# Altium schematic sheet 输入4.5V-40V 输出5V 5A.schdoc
size 384 x 220 mm; SheetNumber: 1; SheetTotal: 1
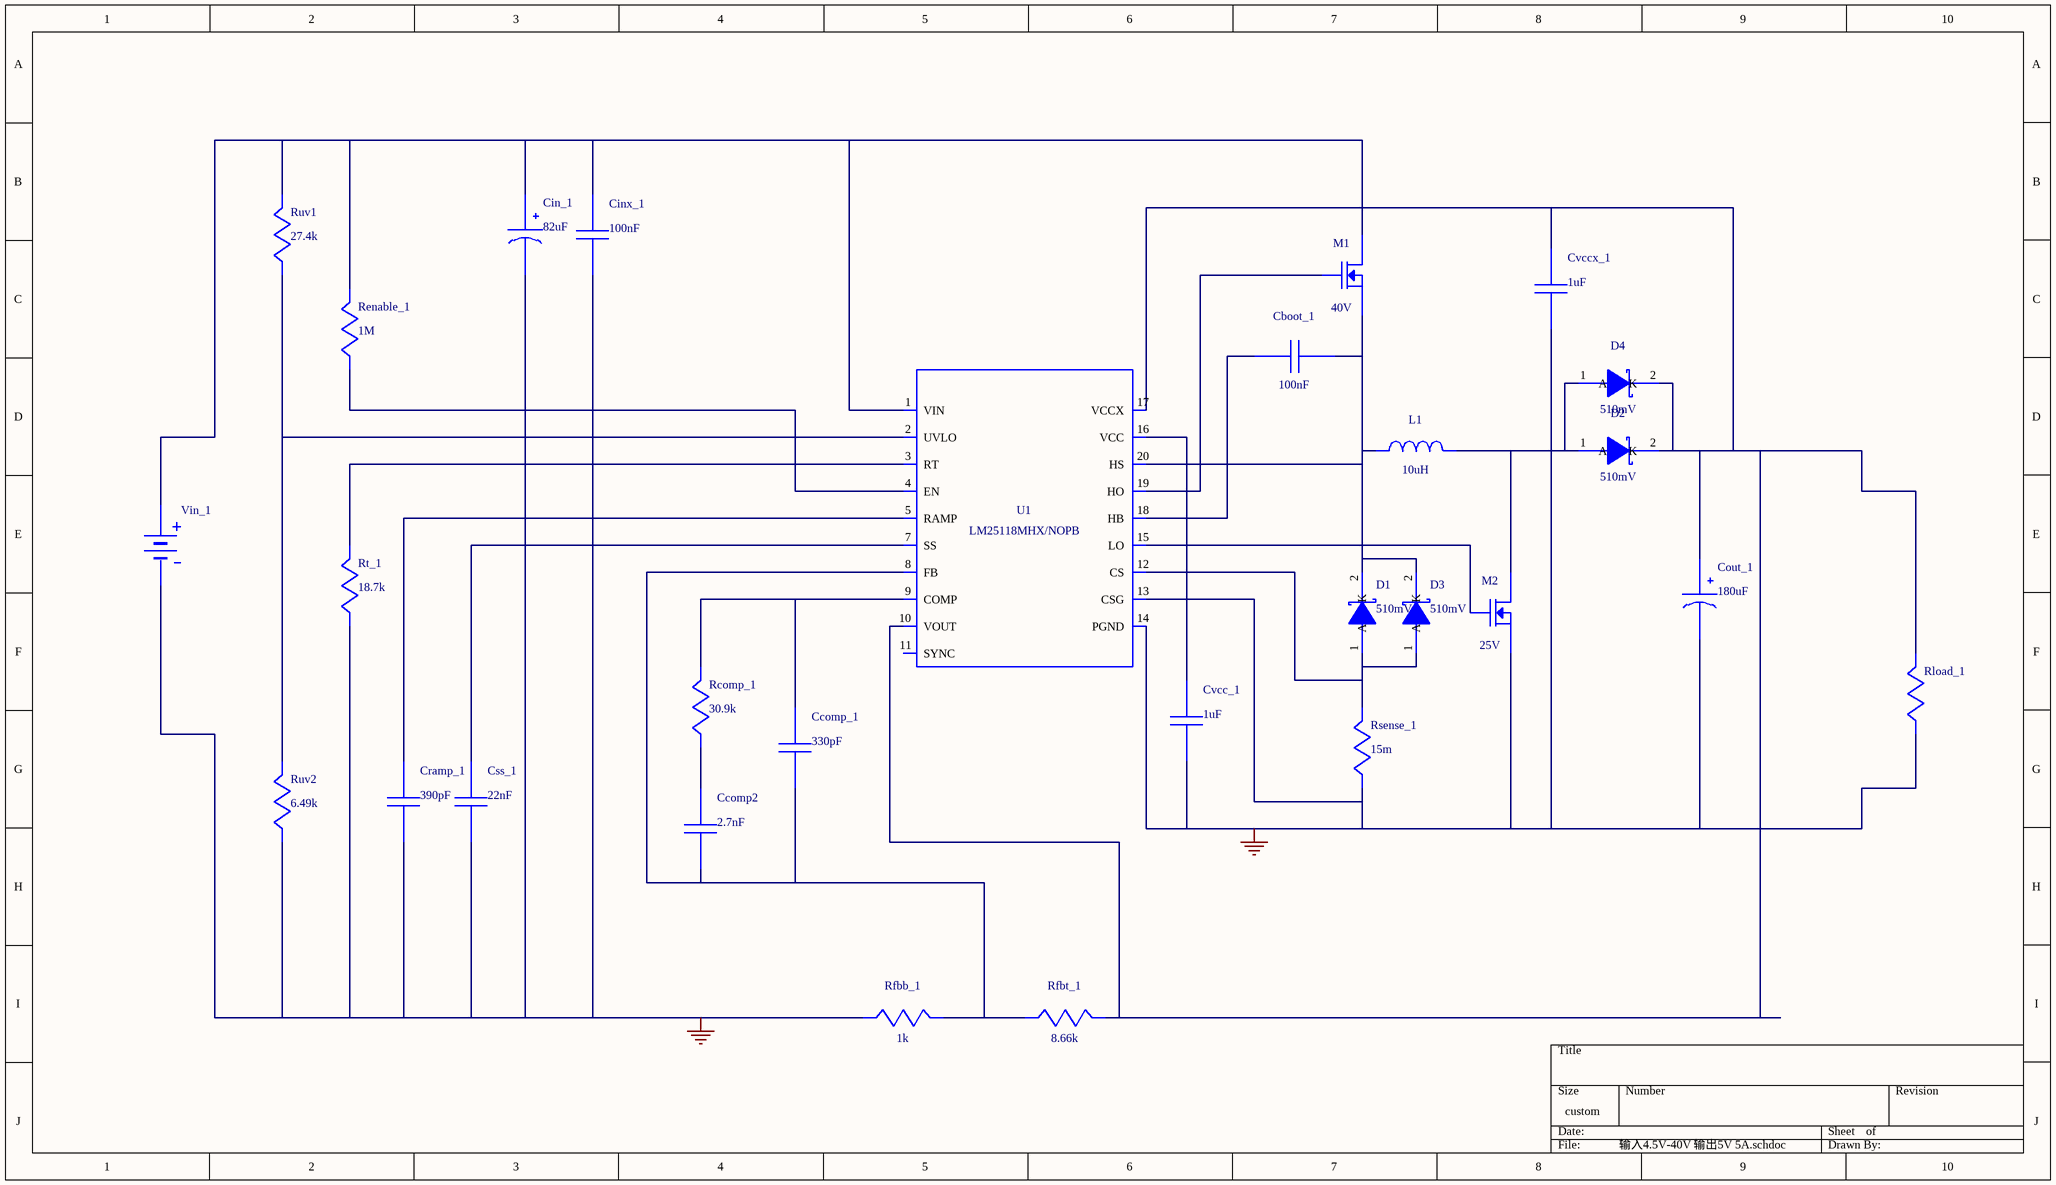
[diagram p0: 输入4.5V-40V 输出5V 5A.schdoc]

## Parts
Cboot_1  value 100nF  (hidden comment: GRM21BR71H104KA01L)
Ccomp2  value 2.7nF  (hidden comment: CC0805KRX7R9BB272)
Ccomp_1  value 330pF  (hidden comment: CC0805KRX7R9BB331)
Cin_1  value 82uF  (hidden comment: 35SVPF82M)
Cinx_1  value 100nF  (hidden comment: C0805C104K5RACTU)
Cout_1  value 180uF  (hidden comment: 16SVPE180M)
Cramp_1  value 390pF  (hidden comment: CC0805KRX7R9BB391)
Css_1  value 22nF  (hidden comment: CC0805KRX7R9BB223)
Cvcc_1  value 1uF  (hidden comment: GRM155R61A105KE15D)
Cvccx_1  value 1uF  (hidden comment: C1608X5R1C105K)
D1  value 510mV  (hidden comment: 50WQ04FNPBF)
D2  value 510mV  (hidden comment: 50WQ04FNPBF)
D3  value 510mV  (hidden comment: 50WQ04FNPBF)
D4  value 510mV  (hidden comment: 50WQ04FNPBF)
L1  value 10uH  (hidden comment: SRP1250-100M)
M1  value 40V  (hidden comment: CSD17306Q5A)
M2  value 25V  (hidden comment: CSD16340Q3)
Rcomp_1  value 30.9k  (hidden comment: CRCW040230K9FKED)
Renable_1  value 1M  (hidden comment: CRCW04021M00FKED)
Rfbb_1  value 1k  (hidden comment: CRCW04021K00FKED)
Rfbt_1  value 8.66k  (hidden comment: CRCW04028K66FKED)
Rload_1  WB_LOAD_RESISTOR  (value not drawn)
Rsense_1  value 15m  (hidden comment: PRL1632-R015-F-T1)
Rt_1  value 18.7k  (hidden comment: CRCW040218K7FKED)
Ruv1  value 27.4k  (hidden comment: CRCW040227K4FKED)
Ruv2  value 6.49k  (hidden comment: CRCW04026K49FKED)
U1  LM25118MHX/NOPB
Vin_1  WB_BATTERY  (value not drawn)

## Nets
0: Cin_1.2(-) Cinx_1.2 Cout_1.2(-) Cramp_1.2 Css_1.2 Cvcc_1.2 Cvccx_1.1 M2.1(Source) M2.2(Source) M2.3(Source) Rfbb_1.2 Rload_1.2 Rsense_1.2 Rt_1.2 Ruv2.2 U1.6(AGND) U1.13(CSG) U1.14(PGND) U1.21(EXP-PAD) Vin_1.2(-)
NetCboot_1_1: Cboot_1.1 D1.2(K) D3.2(K) L1.2 M1.1(Source) M1.2(Source) M1.3(Source) U1.20(HS)
NetCboot_1_2: Cboot_1.2 U1.18(HB)
NetCcomp2_1: Ccomp2.1 Rcomp_1.2
NetCcomp2_2: Ccomp2.2 Ccomp_1.2 Rfbb_1.1 Rfbt_1.2 U1.8(FB)
NetCcomp_1_1: Ccomp_1.1 Rcomp_1.1 U1.9(COMP)
NetCin_1_1: Cin_1.1(+) Cinx_1.1 M1.5(Drain) M1.6(Drain) M1.7(Drain) M1.8(Drain) Renable_1.1 Ruv1.1 U1.1(VIN) Vin_1.1(+)
NetCout_1_1: Cout_1.1(+) Cvccx_1.2 D2.2(K) D4.2(K) Rfbt_1.1 Rload_1.1 U1.10(VOUT) U1.17(VCCX)
NetCramp_1_1: Cramp_1.1 U1.5(RAMP)
NetCss_1_1: Css_1.1 U1.7(SS)
NetCvcc_1_1: Cvcc_1.1 U1.16(VCC)
NetD1_1: D1.1(A) D1.3(A) D3.1(A) D3.3(A) Rsense_1.1 U1.12(CS)
NetD2_1: D2.1(A) D2.3(A) D4.1(A) D4.3(A) L1.1 M2.5(Drain) M2.6(Drain) M2.7(Drain) M2.8(Drain)
NetM1_4: M1.4(Gate) U1.19(HO)
NetM2_4: M2.4(Gate) U1.15(LO)
NetRenable_1_2: Renable_1.2 U1.4(EN)
NetRt_1_1: Rt_1.1 U1.3(RT)
NetRuv1_2: Ruv1.2 Ruv2.1 U1.2(UVLO)

Not connected (* = marked no-connect by the designer): U1 11(SYNC)

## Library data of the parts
Cboot_1 = GRM21BR71H104KA01L: GRM21BR71H104KA0; Manufacturer Name: MuRata
Ccomp2 = CC0805KRX7R9BB272: CC0805KRX7R9BB27; Manufacturer Name: Yageo America
Ccomp_1 = CC0805KRX7R9BB331: CC0805KRX7R9BB33; Manufacturer Name: Yageo America
Cin_1 = 35SVPF82M: Manufacturer Name: Panasonic
Cinx_1 = C0805C104K5RACTU: Manufacturer Name: Kemet
Cout_1 = 16SVPE180M: Manufacturer Name: Panasonic
Cramp_1 = CC0805KRX7R9BB391: CC0805KRX7R9BB39; Manufacturer Name: Yageo America
Css_1 = CC0805KRX7R9BB223: CC0805KRX7R9BB22; Manufacturer Name: Yageo America
Cvcc_1 = GRM155R61A105KE15D: GRM155R61A105KE1; Manufacturer Name: MuRata
Cvccx_1 = C1608X5R1C105K: Manufacturer Name: TDK
D1-D4 = 50WQ04FNPBF: Manufacturer Name: Vishay-Semiconductor
L1 = SRP1250-100M: Manufacturer Name: Bourns
M1 = CSD17306Q5A: CSD18504Q5A; Manufacturer Name: Texas Instruments
M2 = CSD16340Q3: CSD16327Q3; Manufacturer Name: Texas Instruments
Rcomp_1 = CRCW040230K9FKED: Manufacturer Name: Vishay-Dale
Renable_1 = CRCW04021M00FKED: Manufacturer Name: Vishay-Dale
Rfbb_1 = CRCW04021K00FKED: Manufacturer Name: Vishay-Dale
Rfbt_1 = CRCW04028K66FKED: Manufacturer Name: Vishay-Dale
Rload_1 = WB_LOAD_RESISTOR: Value: UNLISTED
Rsense_1 = PRL1632-R015-F-T1: PRL1632-R015-F-T; Manufacturer Name: Susumu Co Ltd
Rt_1 = CRCW040218K7FKED: Manufacturer Name: Vishay-Dale
Ruv1 = CRCW040227K4FKED: Manufacturer Name: Vishay-Dale
Ruv2 = CRCW04026K49FKED: Manufacturer Name: Vishay-Dale
U1 = LM25118MHX/NOPB: Manufacturer Name: Texas Instruments
Vin_1 = WB_BATTERY: Value: UNLISTED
